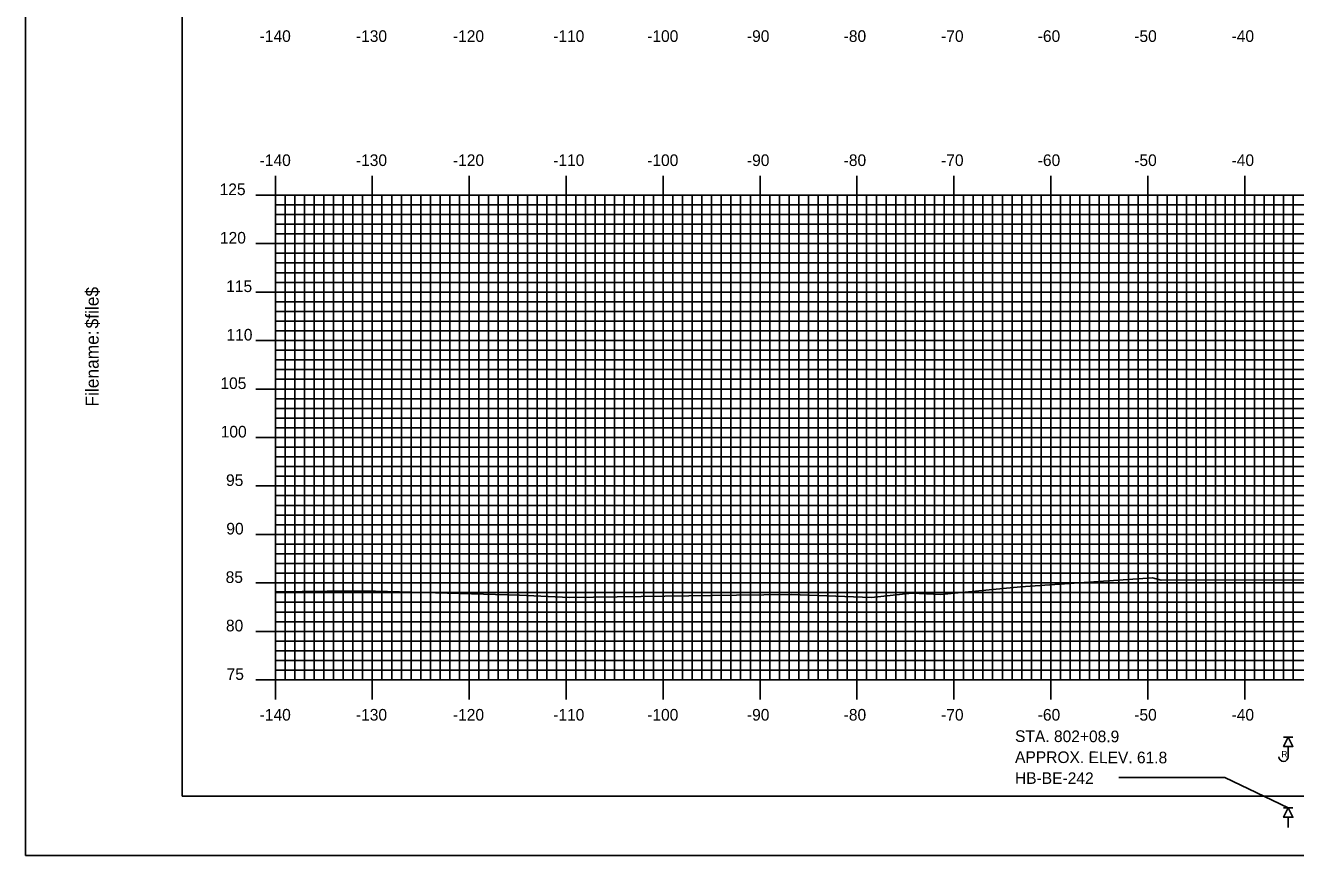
# Model space of a CAD drawing. Extents: x -302 to 42, y -1658 to -1438.
# Drawn here: x -301.7 to -170.6, y -1657.7 to -1572.1 of the extents above; entities that cross this region are included whole.
import ezdxf

# ---------------------------------------------------------------- set-up
doc = ezdxf.new("R2010")
doc.units = 0
for name, color, linetype in [('BORDER', 7, 'Continuous'), ('BORING - NO REFUSAL', 7, 'Continuous'), ('BORING - REFUSAL', 7, 'Continuous'), ('H_V ANNOTATION', 7, 'Continuous'), ('MAJOR', 7, 'Continuous'), ('MINOR', 7, 'Continuous'), ('PLOT BOUNDARY', 7, 'Continuous'), ('S_Roadway_Centerline', 7, 'Continuous')]:
    doc.layers.add(name, color=color, linetype=linetype)

msp = doc.modelspace()

# ---------------------------------------------------------------- linework, layer by layer
at = {"layer": 'BORDER'}
msp.add_lwpolyline([(-285.49, -1651.6), (34.51, -1651.6), (34.51, -1441.6), (-285.49, -1441.6)], close=True, dxfattribs=at)
at = {"layer": 'BORING - NO REFUSAL'}
for p, q in [((-170.91, -1652.8), (-171.87, -1652.8)), ((-171.39, -1653.76), (-171.39, -1654.82))]:
    msp.add_line(p, q, dxfattribs=at)
msp.add_lwpolyline([(-188.89, -1649.67), (-177.95, -1649.67), (-171.39, -1652.8)], dxfattribs=at)
msp.add_lwpolyline([(-171.39, -1652.8), (-170.91, -1653.76), (-171.87, -1653.76)], close=True, dxfattribs=at)
at = {"layer": 'BORING - REFUSAL'}
for p, q in [((-170.91, -1645.5), (-171.87, -1645.5)), ((-171.39, -1646.46), (-171.39, -1647.52))]:
    msp.add_line(p, q, dxfattribs=at)
msp.add_lwpolyline([(-171.39, -1645.5), (-170.91, -1646.46), (-171.87, -1646.46)], close=True, dxfattribs=at)
msp.add_arc((-171.88, -1647.52), 0.485, 180, 0, dxfattribs=at)
at = {"layer": 'MAJOR'}
for p, q in [((-275.89, -1587.6), (-275.89, -1589.6)), ((-265.89, -1587.6), (-265.89, -1589.6)), ((-255.89, -1587.6), (-255.89, -1589.6)), ((-245.89, -1587.6), (-245.89, -1589.6)), ((-235.89, -1587.6), (-235.89, -1589.6)), ((-225.89, -1587.6), (-225.89, -1589.6)), ((-215.89, -1587.6), (-215.89, -1589.6)), ((-205.89, -1587.6), (-205.89, -1589.6)), ((-195.89, -1587.6), (-195.89, -1589.6)), ((-185.89, -1587.6), (-185.89, -1589.6)), ((-175.89, -1587.6), (-175.89, -1589.6)), ((-277.9, -1589.6), (-275.89, -1589.6)), ((-275.89, -1589.6), (4.11, -1589.6)), ((-275.89, -1639.6), (-275.89, -1589.6)), ((-275.89, -1639.6), (-275.89, -1589.6)), ((-275.89, -1589.6), (4.11, -1589.6)), ((-265.89, -1639.6), (-265.89, -1589.6)), ((-255.89, -1639.6), (-255.89, -1589.6)), ((-245.89, -1639.6), (-245.89, -1589.6)), ((-235.89, -1639.6), (-235.89, -1589.6)), ((-225.89, -1639.6), (-225.89, -1589.6)), ((-215.89, -1639.6), (-215.89, -1589.6)), ((-205.89, -1639.6), (-205.89, -1589.6)), ((-195.89, -1639.6), (-195.89, -1589.6)), ((-185.89, -1639.6), (-185.89, -1589.6)), ((-175.89, -1639.6), (-175.89, -1589.6)), ((-277.9, -1594.6), (-275.89, -1594.6)), ((-275.89, -1594.6), (4.11, -1594.6)), ((-277.9, -1599.6), (-275.89, -1599.6)), ((-275.89, -1599.6), (4.11, -1599.6)), ((-277.9, -1604.6), (-275.89, -1604.6)), ((-275.89, -1604.6), (4.11, -1604.6)), ((-277.9, -1609.6), (-275.89, -1609.6)), ((-275.89, -1609.6), (4.11, -1609.6)), ((-277.9, -1614.6), (-275.89, -1614.6)), ((-275.89, -1614.6), (4.11, -1614.6)), ((-277.9, -1619.6), (-275.89, -1619.6)), ((-275.89, -1619.6), (4.11, -1619.6)), ((-277.9, -1624.6), (-275.89, -1624.6)), ((-275.89, -1624.6), (4.11, -1624.6)), ((-277.9, -1629.6), (-275.89, -1629.6)), ((-275.89, -1629.6), (4.11, -1629.6)), ((-277.9, -1634.6), (-275.89, -1634.6)), ((-275.89, -1634.6), (4.11, -1634.6)), ((-277.9, -1639.6), (-275.89, -1639.6)), ((-275.89, -1639.6), (4.11, -1639.6)), ((-275.89, -1639.6), (4.11, -1639.6)), ((-275.89, -1641.61), (-275.89, -1639.6)), ((-265.89, -1641.61), (-265.89, -1639.6)), ((-255.89, -1641.61), (-255.89, -1639.6)), ((-245.89, -1641.61), (-245.89, -1639.6)), ((-235.89, -1641.61), (-235.89, -1639.6)), ((-225.89, -1641.61), (-225.89, -1639.6)), ((-215.89, -1641.61), (-215.89, -1639.6)), ((-205.89, -1641.61), (-205.89, -1639.6)), ((-195.89, -1641.61), (-195.89, -1639.6)), ((-185.89, -1641.61), (-185.89, -1639.6)), ((-175.89, -1641.61), (-175.89, -1639.6))]:
    msp.add_line(p, q, dxfattribs=at)
at = {"layer": 'MINOR'}
for p, q in [((-275.89, -1590.6), (4.11, -1590.6)), ((-275.89, -1590.6), (-273.89, -1590.6)), ((-274.89, -1639.6), (-274.89, -1589.6)), ((-273.89, -1639.6), (-273.89, -1589.6)), ((-272.89, -1639.6), (-272.89, -1589.6)), ((-271.89, -1639.6), (-271.89, -1589.6)), ((-270.89, -1639.6), (-270.89, -1589.6)), ((-269.89, -1639.6), (-269.89, -1589.6)), ((-268.89, -1639.6), (-268.89, -1589.6)), ((-267.89, -1639.6), (-267.89, -1589.6)), ((-266.89, -1639.6), (-266.89, -1589.6)), ((-264.89, -1639.6), (-264.89, -1589.6)), ((-263.89, -1639.6), (-263.89, -1589.6)), ((-262.89, -1639.6), (-262.89, -1589.6)), ((-261.89, -1639.6), (-261.89, -1589.6)), ((-260.89, -1639.6), (-260.89, -1589.6)), ((-259.89, -1639.6), (-259.89, -1589.6)), ((-258.89, -1639.6), (-258.89, -1589.6)), ((-257.89, -1639.6), (-257.89, -1589.6)), ((-256.89, -1639.6), (-256.89, -1589.6)), ((-254.89, -1639.6), (-254.89, -1589.6)), ((-253.89, -1639.6), (-253.89, -1589.6)), ((-252.89, -1639.6), (-252.89, -1589.6)), ((-251.89, -1639.6), (-251.89, -1589.6)), ((-250.89, -1639.6), (-250.89, -1589.6)), ((-249.89, -1639.6), (-249.89, -1589.6)), ((-248.89, -1639.6), (-248.89, -1589.6)), ((-247.89, -1639.6), (-247.89, -1589.6)), ((-246.89, -1639.6), (-246.89, -1589.6)), ((-244.89, -1639.6), (-244.89, -1589.6)), ((-243.89, -1639.6), (-243.89, -1589.6)), ((-242.89, -1639.6), (-242.89, -1589.6)), ((-241.89, -1639.6), (-241.89, -1589.6)), ((-240.89, -1639.6), (-240.89, -1589.6)), ((-239.89, -1639.6), (-239.89, -1589.6)), ((-238.89, -1639.6), (-238.89, -1589.6)), ((-237.89, -1639.6), (-237.89, -1589.6)), ((-236.89, -1639.6), (-236.89, -1589.6)), ((-234.89, -1639.6), (-234.89, -1589.6)), ((-233.89, -1639.6), (-233.89, -1589.6)), ((-232.89, -1639.6), (-232.89, -1589.6)), ((-231.89, -1639.6), (-231.89, -1589.6)), ((-230.89, -1639.6), (-230.89, -1589.6)), ((-229.89, -1639.6), (-229.89, -1589.6)), ((-228.89, -1639.6), (-228.89, -1589.6)), ((-227.89, -1639.6), (-227.89, -1589.6)), ((-226.89, -1639.6), (-226.89, -1589.6)), ((-224.89, -1639.6), (-224.89, -1589.6)), ((-223.89, -1639.6), (-223.89, -1589.6)), ((-222.89, -1639.6), (-222.89, -1589.6)), ((-221.89, -1639.6), (-221.89, -1589.6)), ((-220.89, -1639.6), (-220.89, -1589.6)), ((-219.89, -1639.6), (-219.89, -1589.6)), ((-218.89, -1639.6), (-218.89, -1589.6)), ((-217.89, -1639.6), (-217.89, -1589.6)), ((-216.89, -1639.6), (-216.89, -1589.6)), ((-214.89, -1639.6), (-214.89, -1589.6)), ((-213.89, -1639.6), (-213.89, -1589.6)), ((-212.89, -1639.6), (-212.89, -1589.6)), ((-211.89, -1639.6), (-211.89, -1589.6)), ((-210.89, -1639.6), (-210.89, -1589.6)), ((-209.89, -1639.6), (-209.89, -1589.6)), ((-208.89, -1639.6), (-208.89, -1589.6)), ((-207.89, -1639.6), (-207.89, -1589.6)), ((-206.89, -1639.6), (-206.89, -1589.6)), ((-204.89, -1639.6), (-204.89, -1589.6)), ((-203.89, -1639.6), (-203.89, -1589.6)), ((-202.89, -1639.6), (-202.89, -1589.6)), ((-201.89, -1639.6), (-201.89, -1589.6)), ((-200.89, -1639.6), (-200.89, -1589.6)), ((-199.89, -1639.6), (-199.89, -1589.6)), ((-198.89, -1639.6), (-198.89, -1589.6)), ((-197.89, -1639.6), (-197.89, -1589.6)), ((-196.89, -1639.6), (-196.89, -1589.6)), ((-194.89, -1639.6), (-194.89, -1589.6)), ((-193.89, -1639.6), (-193.89, -1589.6)), ((-192.89, -1639.6), (-192.89, -1589.6)), ((-191.89, -1639.6), (-191.89, -1589.6)), ((-190.89, -1639.6), (-190.89, -1589.6)), ((-189.89, -1639.6), (-189.89, -1589.6)), ((-188.89, -1639.6), (-188.89, -1589.6)), ((-187.89, -1639.6), (-187.89, -1589.6)), ((-186.89, -1639.6), (-186.89, -1589.6)), ((-184.89, -1639.6), (-184.89, -1589.6)), ((-183.89, -1639.6), (-183.89, -1589.6)), ((-182.89, -1639.6), (-182.89, -1589.6)), ((-181.89, -1639.6), (-181.89, -1589.6)), ((-180.89, -1639.6), (-180.89, -1589.6)), ((-179.89, -1639.6), (-179.89, -1589.6)), ((-178.89, -1639.6), (-178.89, -1589.6)), ((-177.89, -1639.6), (-177.89, -1589.6)), ((-176.89, -1639.6), (-176.89, -1589.6)), ((-174.89, -1639.6), (-174.89, -1589.6)), ((-173.89, -1639.6), (-173.89, -1589.6)), ((-172.89, -1639.6), (-172.89, -1589.6)), ((-171.89, -1639.6), (-171.89, -1589.6)), ((-170.89, -1639.6), (-170.89, -1589.6)), ((-275.89, -1591.6), (4.11, -1591.6)), ((-275.89, -1591.6), (-273.89, -1591.6)), ((-275.89, -1592.6), (4.11, -1592.6)), ((-275.89, -1592.6), (-273.89, -1592.6)), ((-275.89, -1593.6), (4.11, -1593.6)), ((-275.89, -1593.6), (-273.89, -1593.6)), ((-275.89, -1595.6), (4.11, -1595.6)), ((-275.89, -1595.6), (-273.89, -1595.6)), ((-275.89, -1596.6), (4.11, -1596.6)), ((-275.89, -1596.6), (-273.89, -1596.6)), ((-275.89, -1597.6), (4.11, -1597.6)), ((-275.89, -1597.6), (-273.89, -1597.6)), ((-275.89, -1598.6), (4.11, -1598.6)), ((-275.89, -1598.6), (-273.89, -1598.6)), ((-275.89, -1600.6), (4.11, -1600.6)), ((-275.89, -1600.6), (-273.89, -1600.6)), ((-275.89, -1601.6), (4.11, -1601.6)), ((-275.89, -1601.6), (-273.89, -1601.6)), ((-275.89, -1602.6), (4.11, -1602.6)), ((-275.89, -1602.6), (-273.89, -1602.6)), ((-275.89, -1603.6), (4.11, -1603.6)), ((-275.89, -1603.6), (-273.89, -1603.6)), ((-275.89, -1605.6), (4.11, -1605.6)), ((-275.89, -1605.6), (-273.89, -1605.6)), ((-275.89, -1606.6), (4.11, -1606.6)), ((-275.89, -1606.6), (-273.89, -1606.6)), ((-275.89, -1607.6), (4.11, -1607.6)), ((-275.89, -1607.6), (-273.89, -1607.6)), ((-275.89, -1608.6), (4.11, -1608.6)), ((-275.89, -1608.6), (-273.89, -1608.6)), ((-275.89, -1610.6), (4.11, -1610.6)), ((-275.89, -1610.6), (-273.89, -1610.6)), ((-275.89, -1611.6), (4.11, -1611.6)), ((-275.89, -1611.6), (-273.89, -1611.6)), ((-275.89, -1612.6), (4.11, -1612.6)), ((-275.89, -1612.6), (-273.89, -1612.6)), ((-275.89, -1613.6), (4.11, -1613.6)), ((-275.89, -1613.6), (-273.89, -1613.6)), ((-275.89, -1615.6), (4.11, -1615.6)), ((-275.89, -1615.6), (-273.89, -1615.6)), ((-275.89, -1616.6), (4.11, -1616.6)), ((-275.89, -1616.6), (-273.89, -1616.6)), ((-275.89, -1617.6), (4.11, -1617.6)), ((-275.89, -1617.6), (-273.89, -1617.6)), ((-275.89, -1618.6), (4.11, -1618.6)), ((-275.89, -1618.6), (-273.89, -1618.6)), ((-275.89, -1620.6), (4.11, -1620.6)), ((-275.89, -1620.6), (-273.89, -1620.6)), ((-275.89, -1621.6), (4.11, -1621.6)), ((-275.89, -1621.6), (-273.89, -1621.6)), ((-275.89, -1622.6), (4.11, -1622.6)), ((-275.89, -1622.6), (-273.89, -1622.6)), ((-275.89, -1623.6), (4.11, -1623.6)), ((-275.89, -1623.6), (-273.89, -1623.6)), ((-275.89, -1625.6), (4.11, -1625.6)), ((-275.89, -1625.6), (-273.89, -1625.6)), ((-275.89, -1626.6), (4.11, -1626.6)), ((-275.89, -1626.6), (-273.89, -1626.6)), ((-275.89, -1627.6), (4.11, -1627.6)), ((-275.89, -1627.6), (-273.89, -1627.6)), ((-275.89, -1628.6), (4.11, -1628.6)), ((-275.89, -1628.6), (-273.89, -1628.6)), ((-275.89, -1630.6), (4.11, -1630.6)), ((-275.89, -1630.6), (-273.89, -1630.6)), ((-275.89, -1631.6), (4.11, -1631.6)), ((-275.89, -1631.6), (-273.89, -1631.6)), ((-275.89, -1632.6), (4.11, -1632.6)), ((-275.89, -1632.6), (-273.89, -1632.6)), ((-275.89, -1633.6), (4.11, -1633.6)), ((-275.89, -1633.6), (-273.89, -1633.6)), ((-275.89, -1635.6), (4.11, -1635.6)), ((-275.89, -1635.6), (-273.89, -1635.6)), ((-275.89, -1636.6), (4.11, -1636.6)), ((-275.89, -1636.6), (-273.89, -1636.6)), ((-275.89, -1637.6), (4.11, -1637.6)), ((-275.89, -1637.6), (-273.89, -1637.6)), ((-275.89, -1638.6), (4.11, -1638.6)), ((-275.89, -1638.6), (-273.89, -1638.6))]:
    msp.add_line(p, q, dxfattribs=at)
at = {"layer": 'PLOT BOUNDARY'}
msp.add_lwpolyline([(-301.68, -1657.72), (38.32, -1657.72), (38.32, -1437.72), (-301.68, -1437.72)], close=True, dxfattribs=at)
at = {"layer": 'S_Roadway_Centerline'}
msp.add_lwpolyline([(-275.89, -1630.52), (-275.74, -1630.52), (-270.54, -1630.44), (-265.57, -1630.44), (-250.72, -1630.86), (-245.53, -1631.11), (-228.32, -1630.87), (-222.68, -1630.8), (-214.38, -1631.1), (-210.22, -1630.66), (-207.24, -1630.78), (-199.02, -1630.01), (-185.4, -1629.07), (-184.52, -1629.3), (-164.65, -1629.28)], dxfattribs=at)

# ---------------------------------------------------------------- texts
at = {"layer": 'BORDER'}
for s, p in [('$file$', (-294.12, -1603.35)), ('Filename:', (-294.12, -1611.41))]:
    msp.add_text(s, height=1.339, rotation=90, dxfattribs=at).set_placement(p)
at = {"layer": 'BORING - NO REFUSAL'}
for s, p in [('STA. 802+08.9', (-199.58, -1646)), ('APPROX. ELEV. 61.8', (-199.58, -1648.16)), ('HB-BE-242', (-199.59, -1650.32))]:
    msp.add_text(s, height=1.2, rotation=359.8142, dxfattribs=at).set_placement(p)
at = {"layer": 'BORING - REFUSAL'}
msp.add_text('R', height=0.64, dxfattribs=at).set_placement((-172.1, -1647.58))
at = {"layer": 'H_V ANNOTATION'}
for s, p in [('-140', (-277.51, -1573.8)), ('-130', (-267.58, -1573.8)), ('-120', (-257.57, -1573.8)), ('-110', (-247.23, -1573.8)), ('-100', (-237.53, -1573.8)), ('-90', (-227.24, -1573.8)), ('-80', (-217.26, -1573.8)), ('-70', (-207.21, -1573.8)), ('-60', (-197.24, -1573.8)), ('-50', (-187.28, -1573.8)), ('-40', (-177.24, -1573.8)), ('-140', (-277.51, -1586.6)), ('-130', (-267.58, -1586.6)), ('-120', (-257.57, -1586.6)), ('-110', (-247.23, -1586.6)), ('-100', (-237.53, -1586.6)), ('-90', (-227.24, -1586.6)), ('-80', (-217.26, -1586.6)), ('-70', (-207.21, -1586.6)), ('-60', (-197.24, -1586.6)), ('-50', (-187.28, -1586.6)), ('-40', (-177.24, -1586.6)), ('125', (-281.64, -1589.6)), ('120', (-281.61, -1594.6)), ('115', (-280.96, -1599.6)), ('110', (-280.93, -1604.6)), ('105', (-281.56, -1609.6)), ('100', (-281.53, -1614.6)), ('95', (-280.98, -1619.6)), ('90', (-280.95, -1624.6)), ('85', (-281.02, -1629.6)), ('80', (-280.99, -1634.6)), ('75', (-280.92, -1639.6)), ('-140', (-277.51, -1643.8)), ('-130', (-267.58, -1643.8)), ('-120', (-257.57, -1643.8)), ('-110', (-247.23, -1643.8)), ('-100', (-237.53, -1643.8)), ('-90', (-227.24, -1643.8)), ('-80', (-217.26, -1643.8)), ('-70', (-207.21, -1643.8)), ('-60', (-197.24, -1643.8)), ('-50', (-187.28, -1643.8)), ('-40', (-177.24, -1643.8))]:
    msp.add_text(s, height=1.2, dxfattribs=at).set_placement(p)
at = {"layer": 'MAJOR'}
msp.add_text('-', height=0.012, dxfattribs=at).set_placement((-275.9, -1639.6))

doc.saveas('drawing.dxf')
